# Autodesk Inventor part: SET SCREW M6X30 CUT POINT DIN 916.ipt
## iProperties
Created: 2006-02
Part Number: SET SCREW M6X30 CUT POINT DIN 916.ipt
Material: Steel, Mild
Description: Hexagon Socket Set Screw
Document SubType Name: Modeling
Standard: DIN 916
Designer: Andy Moles
Standards Organization: DIN
Language: en-US
Size Designation: M6  x  30
Categories: <MemberInstance><Categories><Category DisplayName="Fasteners" InternalName="e4da775c-781d-43d5-af7c-5136215cf5a6" Mnemonic="FSTN"><Category DisplayName="Bolts"
Density: 1 g/cm^3
Author: Andy Moles
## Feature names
1. Body [Revolution]
2. Slot [Extrusion]
3. Chamfer1
4. Chamfer2
